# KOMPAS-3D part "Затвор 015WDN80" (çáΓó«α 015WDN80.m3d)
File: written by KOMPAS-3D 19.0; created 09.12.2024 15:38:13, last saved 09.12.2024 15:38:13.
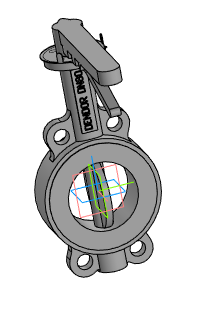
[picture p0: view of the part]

Document properties: Автор: Евгений; Полное имя файла: ..\Затвор 015WDN80.a3d

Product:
- Part/product: Затвор 015WDN80
    Масса: 6.06963

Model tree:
1. Операция без истории:1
